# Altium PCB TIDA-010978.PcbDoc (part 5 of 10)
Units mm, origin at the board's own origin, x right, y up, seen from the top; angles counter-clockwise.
Board outline 243.95 x 94.85 mm, 4 copper layers (Top Layer, Mid Layer 1, Mid Layer 2, Bottom Layer), stack 1.623 mm thick; 865 components, 374 nets, 2308 pads, 2132 vias.
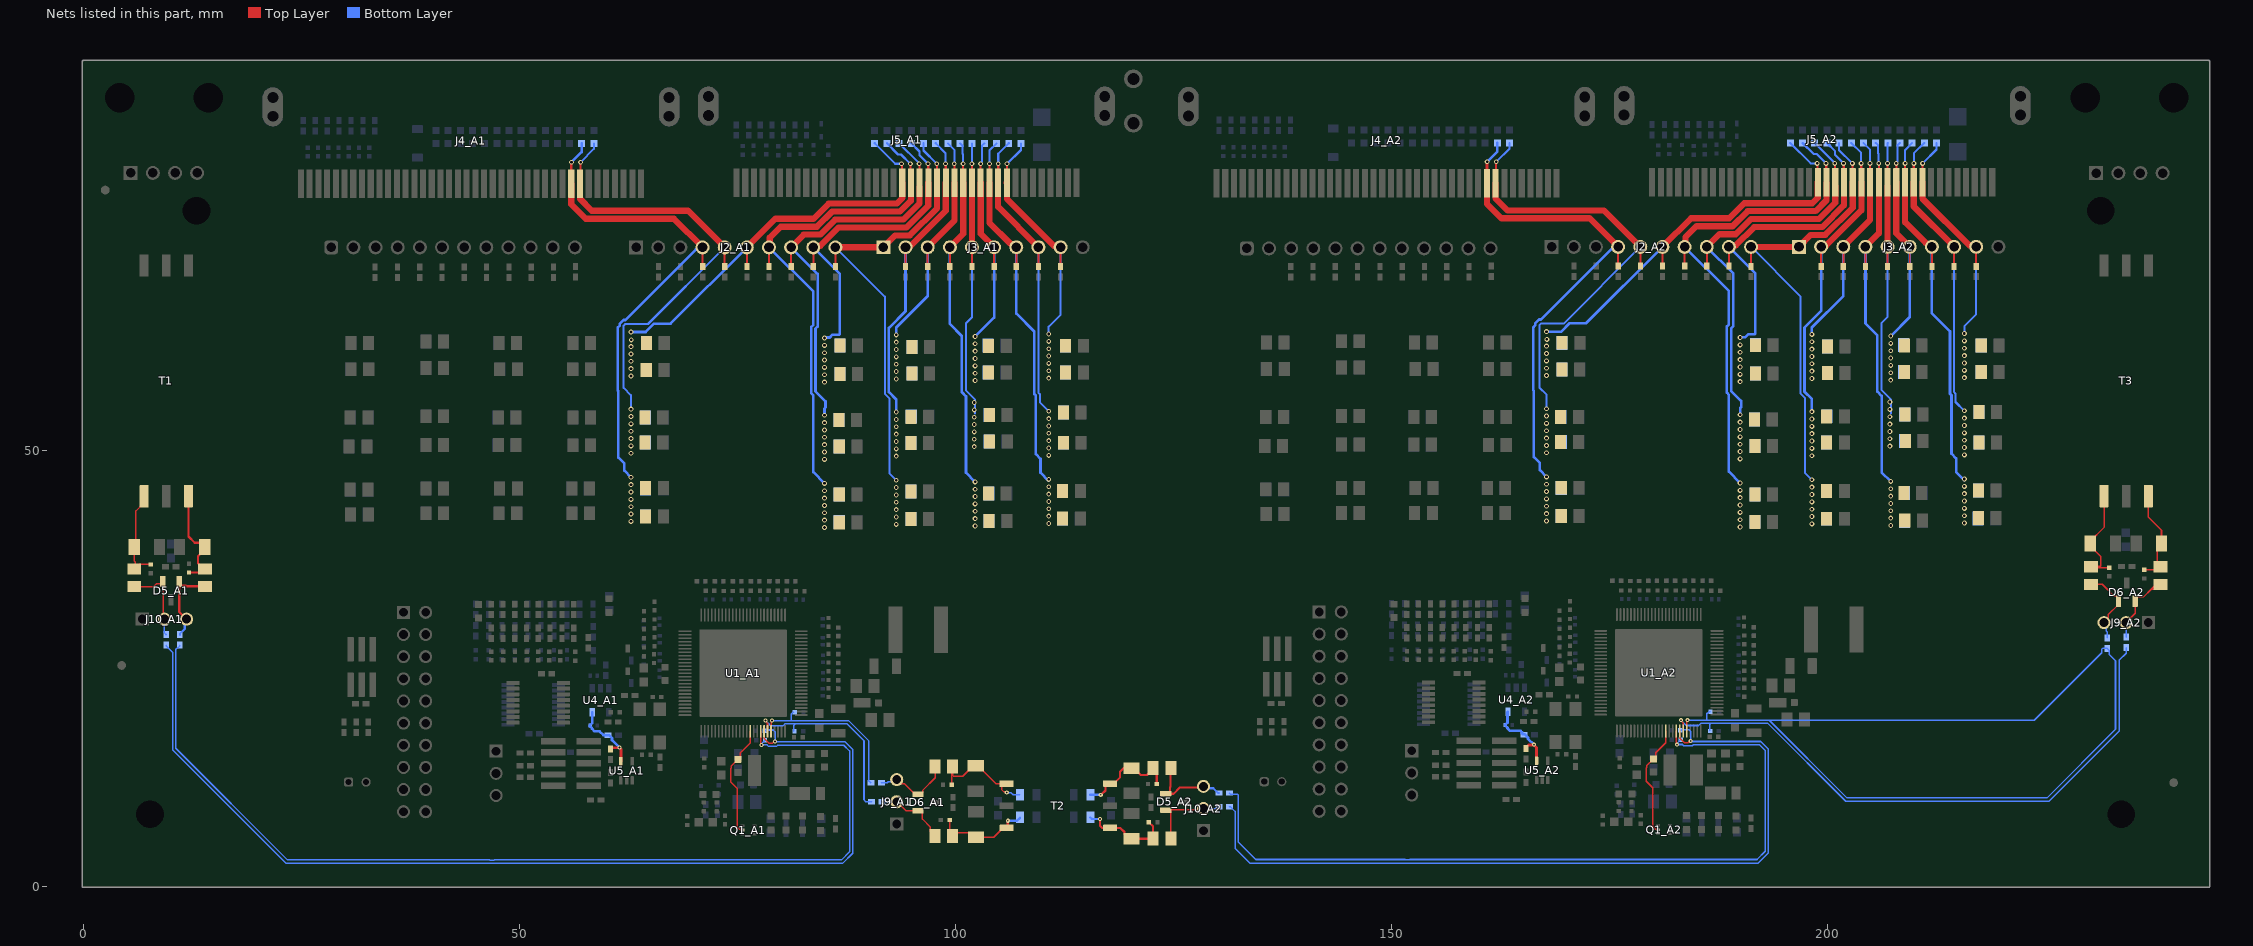
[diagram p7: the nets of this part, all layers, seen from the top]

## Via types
v1: diameter 0.559, hole 0.305, Top Layer to Bottom Layer, tented both sides, 1735 vias
v2: diameter 0.47, hole 0.2, Top Layer to Bottom Layer, tented both sides, 269 vias
v3: diameter 0.5, hole 0.2, Top Layer to Bottom Layer, tented both sides, 128 vias

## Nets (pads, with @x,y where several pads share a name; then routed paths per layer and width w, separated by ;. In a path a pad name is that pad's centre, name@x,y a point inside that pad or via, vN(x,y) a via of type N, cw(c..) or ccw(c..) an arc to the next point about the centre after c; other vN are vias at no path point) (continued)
CELL12_A1: C113_A1.2 J2_A1.4 J4_A1.16 R3_A1.1 R9_A1.1 R13_A1.1 R17_A1.1 R194_A1.1 | length 58.2
  Top Layer w0.229: J2_A1.4@70.993,73.282 71.002,73.273 71.002,71.076 R194_A1.1@71.011,71.067
  Top Layer w0.305: J4_A1.16@55.948,80.581 55.955,80.588 55.955,83.034 v1(55.967,83.046)
  Top Layer w0.711: J4_A1.16@55.948,80.581 55.948,78.226 57.612,76.562 67.714,76.562 J2_A1.4@70.993,73.282
  Bottom Layer w0.305: v1(55.967,83.046) 57.142,84.221 C113_A1.2@57.142,85.209 ; v1(62.782,46.911) 62.021,47.672 62.021,48.484 61.334,49.171 61.334,56.781 61.265,56.85 61.265,64.068 61.482,64.285 61.482,64.499 61.94,64.956 62.153,64.956 70.231,73.034 70.746,73.034 J2_A1.4@70.993,73.282
  other v1: 62.782,41.854 62.782,42.697 62.782,43.54 62.782,44.383 62.782,45.225 62.782,46.068
CELL12_A2: C113_A2.2 J2_A2.4 J4_A2.16 R3_A2.1 R9_A2.1 R13_A2.1 R17_A2.1 R194_A2.1 | length 58.2
  Top Layer w0.229: J2_A2.4@175.993,73.332 176.002,73.323 176.002,71.126 R194_A2.1@176.011,71.117
  Top Layer w0.305: J4_A2.16@160.948,80.631 160.955,80.638 160.955,83.084 v1(160.967,83.096)
  Top Layer w0.711: J4_A2.16@160.948,80.631 160.948,78.276 162.612,76.612 172.714,76.612 J2_A2.4@175.993,73.332
  Bottom Layer w0.305: v1(160.967,83.096) 162.142,84.271 C113_A2.2@162.142,85.259 ; v1(167.782,46.961) 167.021,47.722 167.021,48.534 166.334,49.221 166.334,56.831 166.265,56.9 166.265,64.118 166.482,64.335 166.482,64.549 166.94,65.006 167.153,65.006 175.231,73.084 175.746,73.084 J2_A2.4@175.993,73.332
  other v1: 167.782,41.904 167.782,42.747 167.782,43.59 167.782,44.433 167.782,45.275 167.782,46.118
CELL13_A1: C109_A1.2 J2_A1.5 J4_A1.37 R102_A1.1 R109_A1.1 R114_A1.1 R119_A1.1 R192_A1.1 | length 53.4
  Top Layer w0.229: J4_A1.37@56.942,80.587 56.979,80.624 56.979,83.01 v1(57.016,83.046) ; J2_A1.5@73.533,73.282 73.541,73.275 73.541,71.074 R192_A1.1@73.548,71.067
  Top Layer w0.711: J4_A1.37@56.942,80.587 56.942,78.83 58.299,77.473 69.342,77.473 J2_A1.5@73.533,73.282
  Bottom Layer w0.229: v1(57.016,83.046) 58.533,84.564 C109_A1.2@58.533,85.209 ; v1(62.782,54.727) 62.782,56.325 61.949,57.158 61.949,64.305 62.133,64.489 64.741,64.489 J2_A1.5@73.533,73.282
  other v1: 62.782,49.67 62.782,50.513 62.782,51.356 62.782,52.199 62.782,53.041 62.782,53.884
CELL13_A2: C109_A2.2 J2_A2.5 J4_A2.37 R102_A2.1 R109_A2.1 R114_A2.1 R119_A2.1 R192_A2.1 | length 53.4
  Top Layer w0.229: J4_A2.37@161.942,80.637 161.979,80.674 161.979,83.06 v1(162.016,83.096) ; J2_A2.5@178.533,73.332 178.541,73.325 178.541,71.124 R192_A2.1@178.548,71.117
  Top Layer w0.711: J4_A2.37@161.942,80.637 161.942,78.88 163.299,77.523 174.342,77.523 J2_A2.5@178.533,73.332
  Bottom Layer w0.229: v1(162.016,83.096) 163.533,84.614 C109_A2.2@163.533,85.259 ; v1(167.782,54.777) 167.782,56.375 166.949,57.208 166.949,64.355 167.133,64.539 169.741,64.539 J2_A2.5@178.533,73.332
  other v1: 167.782,49.72 167.782,50.563 167.782,51.406 167.782,52.249 167.782,53.091 167.782,53.934
CELL14_A1: C105_A1.2 J2_A1.6 J5_A1.10 R82_A1.1 R87_A1.1 R92_A1.1 R97_A1.1 R232_A1.1 | length 47.7
  Top Layer w0.229: J2_A1.6@76.073,73.282 76.079,73.276 76.079,71.073 R232_A1.1@76.085,71.067
  Top Layer w0.254: v1(93.817,82.862) 93.855,82.825 93.855,80.725 J5_A1.10@93.892,80.687
  Top Layer w0.711: J2_A1.6@76.073,73.282 79.353,76.562 83.73,76.562 85.464,78.296 93.258,78.296 93.887,78.924 93.887,80.681 J5_A1.10@93.892,80.687
  Bottom Layer w0.254: C105_A1.2@90.742,85.209 93.089,82.862 v1(93.817,82.862)
  Bottom Layer w0.305: v1(62.782,63.569) 64.48,63.569 65.439,64.527 67.319,64.527 J2_A1.6@76.073,73.282
  other v1: 62.782,58.528 62.782,59.371 62.782,60.214 62.782,61.057 62.782,61.9 62.826,62.674
CELL14_A2: C105_A2.2 J2_A2.6 J5_A2.10 R82_A2.1 R87_A2.1 R92_A2.1 R97_A2.1 R232_A2.1 | length 47.7
  Top Layer w0.229: J2_A2.6@181.073,73.332 181.079,73.326 181.079,71.123 R232_A2.1@181.085,71.117
  Top Layer w0.254: v1(198.817,82.912) 198.855,82.875 198.855,80.775 J5_A2.10@198.892,80.737
  Top Layer w0.711: J2_A2.6@181.073,73.332 184.353,76.612 188.73,76.612 190.464,78.346 198.258,78.346 198.887,78.974 198.887,80.731 J5_A2.10@198.892,80.737
  Bottom Layer w0.254: C105_A2.2@195.742,85.259 198.089,82.912 v1(198.817,82.912)
  Bottom Layer w0.305: v1(167.782,63.619) 169.48,63.619 170.439,64.577 172.319,64.577 J2_A2.6@181.073,73.332
  other v1: 167.782,58.578 167.782,59.421 167.782,60.264 167.782,61.107 167.782,61.95 167.826,62.724
CELL15_A1: C103_A1.2 J2_A1.7 J5_A1.31 R60_A1.1 R64_A1.1 R68_A1.1 R74_A1.1 R230_A1.1 | length 59.1
  Top Layer w0.229: J2_A1.7@78.613,73.282 78.618,73.278 78.618,71.071 R230_A1.1@78.622,71.067
  Top Layer w0.254: v1(94.826,82.862) 94.859,82.829 94.859,80.709 J5_A1.31@94.887,80.681
  Top Layer w0.711: J2_A1.7@78.613,73.282 78.713,73.381 78.713,74.4 79.963,75.651 84.108,75.651 85.842,77.385 93.636,77.385 94.887,78.636 J5_A1.31@94.887,80.681
  Bottom Layer w0.254: C103_A1.2@92.139,85.209 93.42,83.928 93.76,83.928 v1(94.826,82.862)
  Bottom Layer w0.305: J2_A1.7@78.613,73.282 83.696,68.199 83.696,64.404 83.451,64.159 83.451,56.562 83.696,56.317 83.696,47.5 v1(84.985,46.212)
  other v1: 84.985,41.154 84.985,41.997 84.985,42.84 84.985,43.683 84.985,44.526 84.985,45.369
CELL15_A2: C103_A2.2 J2_A2.7 J5_A2.31 R60_A2.1 R64_A2.1 R68_A2.1 R74_A2.1 R230_A2.1 | length 59.1
  Top Layer w0.229: J2_A2.7@183.613,73.332 183.618,73.328 183.618,71.121 R230_A2.1@183.622,71.117
  Top Layer w0.254: v1(199.826,82.912) 199.859,82.879 199.859,80.759 J5_A2.31@199.887,80.731
  Top Layer w0.711: J2_A2.7@183.613,73.332 183.713,73.431 183.713,74.45 184.963,75.701 189.108,75.701 190.842,77.435 198.636,77.435 199.887,78.686 J5_A2.31@199.887,80.731
  Bottom Layer w0.254: C103_A2.2@197.139,85.259 198.42,83.978 198.76,83.978 v1(199.826,82.912)
  Bottom Layer w0.305: J2_A2.7@183.613,73.332 188.696,68.249 188.696,64.454 188.451,64.209 188.451,56.612 188.696,56.367 188.696,47.55 v1(189.985,46.262)
  other v1: 189.985,41.204 189.985,42.047 189.985,42.89 189.985,43.733 189.985,44.576 189.985,45.419
CELL16_A1: C99_A1.2 J2_A1.8 J5_A1.11 R40_A1.1 R44_A1.1 R48_A1.1 R53_A1.1 R224_A1.1 | length 48
  Top Layer w0.229: J2_A1.8@81.153,73.282 81.156,73.279 81.156,71.07 R224_A1.1@81.159,71.067
  Top Layer w0.254: v1(95.834,82.862) 95.863,82.833 95.863,80.299 J5_A1.11@95.887,80.276
  Top Layer w0.711: J2_A1.8@81.153,73.282 82.611,74.74 84.485,74.74 86.219,76.473 94.013,76.473 95.887,78.347 J5_A1.11@95.887,80.276
  Bottom Layer w0.254: C99_A1.2@93.536,85.209 95.834,82.911 v1(95.834,82.862)
  Bottom Layer w0.305: J2_A1.8@81.153,73.282 84.201,70.234 84.201,64.195 83.956,63.95 83.956,56.771 85.1,55.627 85.1,54.919 84.985,54.804 v1(84.985,54.028)
  other v1: 84.985,48.97 84.985,49.813 84.985,50.656 84.985,51.499 84.985,52.342 84.985,53.185
CELL16_A2: C99_A2.2 J2_A2.8 J5_A2.11 R40_A2.1 R44_A2.1 R48_A2.1 R53_A2.1 R224_A2.1 | length 48
  Top Layer w0.229: J2_A2.8@186.153,73.332 186.156,73.329 186.156,71.12 R224_A2.1@186.159,71.117
  Top Layer w0.254: v1(200.834,82.912) 200.863,82.883 200.863,80.349 J5_A2.11@200.887,80.326
  Top Layer w0.711: J2_A2.8@186.153,73.332 187.611,74.79 189.485,74.79 191.219,76.523 199.013,76.523 200.887,78.397 J5_A2.11@200.887,80.326
  Bottom Layer w0.254: C99_A2.2@198.536,85.259 200.834,82.961 v1(200.834,82.912)
  Bottom Layer w0.305: J2_A2.8@186.153,73.332 189.201,70.284 189.201,64.245 188.956,64 188.956,56.821 190.1,55.677 190.1,54.969 189.985,54.854 v1(189.985,54.078)
  other v1: 189.985,49.02 189.985,49.863 189.985,50.706 189.985,51.549 189.985,52.392 189.985,53.235
CELL17_A1: C96_A1.2 J2_A1.9 J5_A1.32 R23_A1.1 R27_A1.1 R31_A1.1 R35_A1.1 R220_A1.1 | length 38.5
  Top Layer w0.229: J2_A1.9@83.693,73.282 83.695,73.281 83.695,71.068 R220_A1.1@83.696,71.067
  Top Layer w0.254: v1(96.842,82.862) 96.867,82.837 96.867,80.701 J5_A1.32@96.887,80.681
  Top Layer w0.711: J2_A1.9@83.693,73.282 83.863,73.452 84.486,73.452 86.596,75.562 94.39,75.562 96.887,78.059 J5_A1.32@96.887,80.681
  Bottom Layer w0.254: C96_A1.2@94.934,85.209 95.877,84.265 95.877,83.828 v1(96.842,82.862)
  Bottom Layer w0.305: J2_A1.9@83.693,73.282 86.735,70.241 86.735,63.347 86.658,63.27 85.917,63.27 85.582,62.935 85.033,62.935 v1(84.985,62.886)
  other v1: 84.985,57.829 84.985,58.671 84.985,59.514 84.985,60.357 84.985,61.2 84.985,62.043
CELL17_A2: C96_A2.2 J2_A2.9 J5_A2.32 R23_A2.1 R27_A2.1 R31_A2.1 R35_A2.1 R220_A2.1 | length 38.5
  Top Layer w0.229: J2_A2.9@188.693,73.332 188.695,73.331 188.695,71.118 R220_A2.1@188.696,71.117
  Top Layer w0.254: v1(201.842,82.912) 201.867,82.887 201.867,80.751 J5_A2.32@201.887,80.731
  Top Layer w0.711: J2_A2.9@188.693,73.332 188.863,73.502 189.486,73.502 191.596,75.612 199.39,75.612 201.887,78.109 J5_A2.32@201.887,80.731
  Bottom Layer w0.254: C96_A2.2@199.934,85.259 200.877,84.315 200.877,83.878 v1(201.842,82.912)
  Bottom Layer w0.305: J2_A2.9@188.693,73.332 191.735,70.291 191.735,63.397 191.658,63.32 190.917,63.32 190.582,62.985 190.033,62.985 v1(189.985,62.936)
  other v1: 189.985,57.879 189.985,58.721 189.985,59.564 189.985,60.407 189.985,61.25 189.985,62.093
CELL18_A1: C93_A1.2 J2_A1.10 J3_A1.1 J5_A1.12 R4_A1.1 R10_A1.1 R14_A1.1 R18_A1.1 R217_A1.1 | length 53.4
  Top Layer w0.229: R217_A1.1@86.233,71.067 J2_A1.10@86.233,73.282
  Top Layer w0.254: v1(97.851,82.862) 97.871,82.841 97.871,80.708 J5_A1.12@97.892,80.687
  Top Layer w0.711: J2_A1.10@86.233,73.282 86.24,73.289 91.728,73.289 J3_A1.1@91.735,73.295 93.09,74.651 94.768,74.651 97.892,77.775 J5_A1.12@97.892,80.687
  Bottom Layer w0.229: J2_A1.10@86.233,73.282 91.896,67.62 91.896,56.48 92.446,55.93 92.446,47.34 v1(93.21,46.576)
  Bottom Layer w0.254: C93_A1.2@96.331,85.209 96.331,84.382 v1(97.851,82.862)
  other v1: 93.21,41.519 93.21,42.362 93.21,43.204 93.21,44.047 93.21,44.89 93.21,45.733
CELL18_A2: C93_A2.2 J2_A2.10 J3_A2.1 J5_A2.12 R4_A2.1 R10_A2.1 R14_A2.1 R18_A2.1 R217_A2.1 | length 53.4
  Top Layer w0.229: R217_A2.1@191.233,71.117 J2_A2.10@191.233,73.332
  Top Layer w0.254: v1(202.851,82.912) 202.871,82.891 202.871,80.758 J5_A2.12@202.892,80.737
  Top Layer w0.711: J2_A2.10@191.233,73.332 191.24,73.339 196.728,73.339 J3_A2.1@196.735,73.345 198.09,74.701 199.768,74.701 202.892,77.825 J5_A2.12@202.892,80.737
  Bottom Layer w0.229: J2_A2.10@191.233,73.332 196.896,67.67 196.896,56.53 197.446,55.98 197.446,47.39 v1(198.21,46.626)
  Bottom Layer w0.254: C93_A2.2@201.331,85.259 201.331,84.432 v1(202.851,82.912)
  other v1: 198.21,41.569 198.21,42.412 198.21,43.254 198.21,44.097 198.21,44.94 198.21,45.783
CELL19_A1: C90_A1.2 J3_A1.2 J5_A1.33 R103_A1.1 R110_A1.1 R115_A1.1 R120_A1.1 R214_A1.1 | length 36.8
  Top Layer w0.229: R214_A1.1@94.275,71.062 J3_A1.2@94.275,73.295
  Top Layer w0.254: v1(98.859,82.862) 98.876,82.845 98.876,80.704 J5_A1.33@98.892,80.687
  Top Layer w0.711: J3_A1.2@94.275,73.295 94.445,73.465 94.871,73.465 98.892,77.487 J5_A1.33@98.892,80.687
  Bottom Layer w0.254: C90_A1.2@97.728,85.209 98.859,84.077 v1(98.859,82.862)
  Bottom Layer w0.305: v1(93.21,54.392) 93.21,55.825 92.362,56.673 92.362,64.041 94.275,65.953 J3_A1.2@94.275,73.295
  other v1: 93.21,49.335 93.21,50.178 93.21,51.02 93.21,51.863 93.21,52.706 93.21,53.549
CELL19_A2: C90_A2.2 J3_A2.2 J5_A2.33 R103_A2.1 R110_A2.1 R115_A2.1 R120_A2.1 R214_A2.1 | length 36.8
  Top Layer w0.229: R214_A2.1@199.275,71.112 J3_A2.2@199.275,73.345
  Top Layer w0.254: v1(203.859,82.912) 203.876,82.895 203.876,80.754 J5_A2.33@203.892,80.737
  Top Layer w0.711: J3_A2.2@199.275,73.345 199.445,73.515 199.871,73.515 203.892,77.537 J5_A2.33@203.892,80.737
  Bottom Layer w0.254: C90_A2.2@202.728,85.259 203.859,84.127 v1(203.859,82.912)
  Bottom Layer w0.305: v1(198.21,54.442) 198.21,55.875 197.362,56.723 197.362,64.091 199.275,66.003 J3_A2.2@199.275,73.345
  other v1: 198.21,49.385 198.21,50.228 198.21,51.07 198.21,51.913 198.21,52.756 198.21,53.599
CELL20_A1: C87_A1.2 J3_A1.3 J5_A1.13 R83_A1.1 R88_A1.1 R93_A1.1 R98_A1.1 R208_A1.1 | length 27.3
  Top Layer w0.229: R208_A1.1@96.815,71.062 J3_A1.3@96.815,73.295 ; v1(99.867,82.862) 99.88,82.85 99.88,80.7 J5_A1.13@99.892,80.687
  Top Layer w0.711: J3_A1.3@96.815,73.295 99.892,76.373 J5_A1.13@99.892,80.687
  Bottom Layer w0.229: C87_A1.2@99.125,85.209 99.867,84.466 v1(99.867,82.862)
  Bottom Layer w0.305: v1(93.21,63.25) 93.21,64.069 96.815,67.673 J3_A1.3@96.815,73.295
  other v1: 93.21,58.193 93.21,59.036 93.21,59.879 93.21,60.722 93.21,61.565 93.21,62.407
CELL20_A2: C87_A2.2 J3_A2.3 J5_A2.13 R83_A2.1 R88_A2.1 R93_A2.1 R98_A2.1 R208_A2.1 | length 27.3
  Top Layer w0.229: R208_A2.1@201.815,71.112 J3_A2.3@201.815,73.345 ; v1(204.867,82.912) 204.88,82.9 204.88,80.75 J5_A2.13@204.892,80.737
  Top Layer w0.711: J3_A2.3@201.815,73.345 204.892,76.423 J5_A2.13@204.892,80.737
  Bottom Layer w0.229: C87_A2.2@204.125,85.259 204.867,84.516 v1(204.867,82.912)
  Bottom Layer w0.305: v1(198.21,63.3) 198.21,64.119 201.815,67.723 J3_A2.3@201.815,73.345
  other v1: 198.21,58.243 198.21,59.086 198.21,59.929 198.21,60.772 198.21,61.615 198.21,62.457
CELL21_A1: C85_A1.2 J3_A1.4 J5_A1.34 R61_A1.1 R65_A1.1 R69_A1.1 R75_A1.1 R206_A1.1 | length 43
  Top Layer w0.229: R206_A1.1@99.355,71.062 J3_A1.4@99.355,73.295 ; v1(100.876,82.862) 100.884,82.854 100.884,80.695 J5_A1.34@100.892,80.687
  Top Layer w0.711: J3_A1.4@99.355,73.295 100.892,74.833 J5_A1.34@100.892,80.687
  Bottom Layer w0.229: C85_A1.2@100.522,85.209 100.808,84.923 100.808,84.003 100.876,83.935 v1(100.876,82.862)
  Bottom Layer w0.305: J3_A1.4@99.355,73.295 99.355,64.502 100.721,63.136 100.721,56.684 101.212,56.193 101.212,47.435 v1(102.257,46.39)
  other v1: 102.257,41.333 102.257,42.176 102.257,43.019 102.257,43.861 102.257,44.704 102.257,45.547
CELL21_A2: C85_A2.2 J3_A2.4 J5_A2.34 R61_A2.1 R65_A2.1 R69_A2.1 R75_A2.1 R206_A2.1 | length 43
  Top Layer w0.229: R206_A2.1@204.355,71.112 J3_A2.4@204.355,73.345 ; v1(205.876,82.912) 205.884,82.904 205.884,80.745 J5_A2.34@205.892,80.737
  Top Layer w0.711: J3_A2.4@204.355,73.345 205.892,74.883 J5_A2.34@205.892,80.737
  Bottom Layer w0.229: C85_A2.2@205.522,85.259 205.808,84.973 205.808,84.053 205.876,83.985 v1(205.876,82.912)
  Bottom Layer w0.305: J3_A2.4@204.355,73.345 204.355,64.552 205.721,63.186 205.721,56.734 206.212,56.243 206.212,47.485 v1(207.257,46.44)
  other v1: 207.257,41.383 207.257,42.226 207.257,43.069 207.257,43.911 207.257,44.754 207.257,45.597
CELL22_A1: C83_A1.2 J3_A1.5 J5_A1.14 R41_A1.1 R45_A1.1 R49_A1.1 R54_A1.1 R204_A1.1 | length 34
  Top Layer w0.229: v1(101.884,82.862) 101.888,82.858 101.888,80.281 J5_A1.14@101.894,80.276 ; R204_A1.1@101.895,71.062 J3_A1.5@101.895,73.295
  Top Layer w0.711: J5_A1.14@101.894,80.276 J3_A1.5@101.895,73.295 J3_A1.5@101.895,73.295
  Bottom Layer w0.229: v1(101.884,82.862) 101.884,85.173 C83_A1.2@101.919,85.209 ; J3_A1.5@101.895,73.295 101.895,65.254 101.188,64.548 101.188,56.878 102.257,55.808 102.257,54.206
  other v1: 102.153,50.433 102.153,51.276 102.153,52.119 102.153,52.962 102.153,53.805 102.153,54.648 102.153,55.491
CELL22_A2: C83_A2.2 J3_A2.5 J5_A2.14 R41_A2.1 R45_A2.1 R49_A2.1 R54_A2.1 R204_A2.1 | length 34
  Top Layer w0.229: v1(206.884,82.912) 206.888,82.908 206.888,80.331 J5_A2.14@206.894,80.326 ; R204_A2.1@206.895,71.112 J3_A2.5@206.895,73.345
  Top Layer w0.711: J5_A2.14@206.894,80.326 206.894,73.347 J3_A2.5@206.895,73.345
  Bottom Layer w0.229: v1(206.884,82.912) 206.884,85.223 C83_A2.2@206.919,85.259 ; J3_A2.5@206.895,73.345 206.895,65.304 206.188,64.598 206.188,56.928 207.257,55.858 207.257,54.256
  other v1: 207.153,50.483 207.153,51.326 207.153,52.169 207.153,53.012 207.153,53.855 207.153,54.698 207.153,55.541
CELL23_A1: C79_A1.2 J3_A1.6 J5_A1.35 R24_A1.1 R28_A1.1 R32_A1.1 R36_A1.1 R202_A1.1 | length 26.1
  Top Layer w0.229: J5_A1.35@102.892,80.687 v1(102.892,82.862) ; R202_A1.1@104.435,71.062 J3_A1.6@104.435,73.295
  Top Layer w0.711: J5_A1.35@102.892,80.687 102.892,74.838 J3_A1.6@104.435,73.295
  Bottom Layer w0.229: v1(102.892,82.862) 102.892,82.951 103.03,83.09 103.03,84.923 C79_A1.2@103.316,85.209
  Bottom Layer w0.305: v1(102.257,63.065) 104.435,65.242 J3_A1.6@104.435,73.295
  other v1: 102.257,58.007 102.257,58.85 102.257,59.693 102.257,60.536 102.257,61.379 102.257,62.222
CELL23_A2: C79_A2.2 J3_A2.6 J5_A2.35 R24_A2.1 R28_A2.1 R32_A2.1 R36_A2.1 R202_A2.1 | length 26.1
  Top Layer w0.229: J5_A2.35@207.892,80.737 v1(207.892,82.912) ; R202_A2.1@209.435,71.112 J3_A2.6@209.435,73.345
  Top Layer w0.711: J5_A2.35@207.892,80.737 207.892,74.888 J3_A2.6@209.435,73.345
  Bottom Layer w0.229: v1(207.892,82.912) 207.892,83.001 208.03,83.14 208.03,84.973 C79_A2.2@208.316,85.259
  Bottom Layer w0.305: v1(207.257,63.115) 209.435,65.292 J3_A2.6@209.435,73.345
  other v1: 207.257,58.057 207.257,58.9 207.257,59.743 207.257,60.586 207.257,61.429 207.257,62.272
CELL24_A1: C75_A1.2 J3_A1.7 J5_A1.15 R5_A1.1 R11_A1.1 R15_A1.1 R19_A1.1 R200_A1.1 | length 44.4
  Top Layer w0.229: J5_A1.15@103.892,80.687 103.896,80.691 103.896,82.858 v1(103.901,82.862) ; R200_A1.1@106.975,71.062 J3_A1.7@106.975,73.295
  Top Layer w0.711: J5_A1.15@103.892,80.687 103.892,76.1 106.252,73.74 106.29,73.74 106.734,73.295 J3_A1.7@106.975,73.295
  Bottom Layer w0.229: v1(103.901,82.862) 103.901,84.396 C75_A1.2@104.713,85.209
  Bottom Layer w0.305: J3_A1.7@106.975,73.295 106.975,65.67 109.043,63.602 109.043,56.444 109.217,56.27 109.217,49.569 109.756,49.029 109.756,47.447 110.693,46.51 v1(110.693,46.671)
  other v1: 110.693,41.613 110.693,42.456 110.693,43.299 110.693,44.142 110.693,44.985 110.693,45.828
CELL24_A2: C75_A2.2 J3_A2.7 J5_A2.15 R5_A2.1 R11_A2.1 R15_A2.1 R19_A2.1 R200_A2.1 | length 44.4
  Top Layer w0.229: J5_A2.15@208.892,80.737 208.896,80.741 208.896,82.908 v1(208.901,82.912) ; R200_A2.1@211.975,71.112 J3_A2.7@211.975,73.345
  Top Layer w0.711: J5_A2.15@208.892,80.737 208.892,76.15 211.252,73.79 211.29,73.79 211.734,73.345 J3_A2.7@211.975,73.345
  Bottom Layer w0.229: v1(208.901,82.912) 208.901,84.446 C75_A2.2@209.713,85.259
  Bottom Layer w0.305: J3_A2.7@211.975,73.345 211.975,65.72 214.043,63.652 214.043,56.494 214.217,56.32 214.217,49.619 214.756,49.079 214.756,47.497 215.693,46.56 v1(215.693,46.721)
  other v1: 215.693,41.663 215.693,42.506 215.693,43.349 215.693,44.192 215.693,45.035 215.693,45.878
CELL25_A1: C71_A1.2 J3_A1.8 J5_A1.36 R104_A1.1 R111_A1.1 R116_A1.1 R121_A1.1 R198_A1.1 | length 35.9
  Top Layer w0.229: R198_A1.1@109.515,71.062 J3_A1.8@109.515,73.295
  Top Layer w0.254: J5_A1.36@104.892,80.687 104.901,80.695 104.901,82.854 v1(104.909,82.862)
  Top Layer w0.711: J5_A1.36@104.892,80.687 104.892,77.918 J3_A1.8@109.515,73.295
  Bottom Layer w0.229: J3_A1.8@109.515,73.295 109.515,56.632 109.683,56.463 109.683,55.496 v1(110.693,54.487)
  Bottom Layer w0.254: v1(104.909,82.862) 104.909,84.007 C71_A1.2@106.11,85.209
  other v1: 110.693,49.429 110.693,50.272 110.693,51.115 110.693,51.958 110.693,52.801 110.693,53.644
CELL25_A2: C71_A2.2 J3_A2.8 J5_A2.36 R104_A2.1 R111_A2.1 R116_A2.1 R121_A2.1 R198_A2.1 | length 35.9
  Top Layer w0.229: R198_A2.1@214.515,71.112 J3_A2.8@214.515,73.345
  Top Layer w0.254: J5_A2.36@209.892,80.737 209.901,80.745 209.901,82.904 v1(209.909,82.912)
  Top Layer w0.711: J5_A2.36@209.892,80.737 209.892,77.968 J3_A2.8@214.515,73.345
  Bottom Layer w0.229: J3_A2.8@214.515,73.345 214.515,56.682 214.683,56.513 214.683,55.546 v1(215.693,54.537)
  Bottom Layer w0.254: v1(209.909,82.912) 209.909,84.057 C71_A2.2@211.11,85.259
  other v1: 215.693,49.479 215.693,50.322 215.693,51.165 215.693,52.008 215.693,52.851 215.693,53.694
CELL26_A1: C70_A1.2 J3_A1.9 J5_A1.16 R84_A1.1 R89_A1.1 R94_A1.1 R99_A1.1 R195_A1.1 | length 28.2
  Top Layer w0.229: R195_A1.1@112.055,71.062 J3_A1.9@112.055,73.295
  Top Layer w0.254: J5_A1.16@105.892,80.687 105.905,80.7 105.905,82.85 v1(105.917,82.862)
  Top Layer w0.711: J5_A1.16@105.892,80.687 105.898,80.681 105.898,78.829 111.262,73.465 111.885,73.465 J3_A1.9@112.055,73.295
  Bottom Layer w0.229: v1(110.693,63.345) 110.693,64.18 112.055,65.542 J3_A1.9@112.055,73.295
  Bottom Layer w0.254: v1(105.917,82.862) 107.507,84.452 C70_A1.2@107.507,85.197
  other v1: 110.693,58.288 110.693,59.131 110.693,59.973 110.693,60.816 110.693,61.659 110.693,62.502
CELL26_A2: C70_A2.2 J3_A2.9 J5_A2.16 R84_A2.1 R89_A2.1 R94_A2.1 R99_A2.1 R195_A2.1 | length 28.2
  Top Layer w0.229: R195_A2.1@217.055,71.112 J3_A2.9@217.055,73.345
  Top Layer w0.254: J5_A2.16@210.892,80.737 210.905,80.75 210.905,82.9 v1(210.917,82.912)
  Top Layer w0.711: J5_A2.16@210.892,80.737 210.898,80.731 210.898,78.879 216.262,73.515 216.885,73.515 J3_A2.9@217.055,73.345
  Bottom Layer w0.229: v1(215.693,63.395) 215.693,64.23 217.055,65.592 J3_A2.9@217.055,73.345
  Bottom Layer w0.254: v1(210.917,82.912) 212.507,84.502 C70_A2.2@212.507,85.247
  other v1: 215.693,58.338 215.693,59.181 215.693,60.023 215.693,60.866 215.693,61.709 215.693,62.552
COMH_A1_N: C151_A1.2 R227_A1.1 U1_A1.95 | length 22.4
  Top Layer w0.178: v2(78.214,19.014) 78.214,18.935 78.446,18.702 78.446,17.785 U1_A1.95@78.457,17.774
  Bottom Layer w0.178: v2(78.214,19.014) 78.7,18.528 78.7,18.503 78.804,18.399 80.22,18.399 80.457,18.636 81.624,18.636 ; C151_A1.2@81.478,17.806 81.478,18.49 81.624,18.636 ; R227_A1.1@90.391,9.702 89.724,9.702 89.509,9.917 89.509,16.701 87.574,18.636 81.624,18.636
COMH_A1_P: C139_A1.1 R211_A1.1 U1_A1.96 | length 19.4
  Top Layer w0.178: U1_A1.96@78.857,17.774 78.868,17.785 78.868,18.848 78.955,18.935 v2(78.955,19.014)
  Bottom Layer w0.178: v2(78.955,19.014) 80.327,19.014 81.161,19.014 ; C139_A1.1@81.479,19.959 81.379,19.959 81.168,19.748 81.168,19.648 81.161,19.641 81.161,19.014 ; R211_A1.1@90.306,11.874 90.285,11.874 90.074,12.085 90.074,16.67 87.731,19.014 81.161,19.014
COMH_A2_N: C151_A2.2 R227_A2.1 U1_A2.95 | length 69.8
  Top Layer w0.178: v2(183.214,19.064) 183.214,18.985 183.446,18.752 183.446,17.835 U1_A2.95@183.457,17.824
  Bottom Layer w0.178: v2(183.214,19.064) 183.7,18.578 183.7,18.553 183.804,18.449 185.22,18.449 185.457,18.686 186.624,18.686 ; C151_A2.2@186.478,17.856 186.478,18.54 186.624,18.686 ; R227_A2.1@234.25,27.375 234.25,26.725 233.471,25.946 233.471,17.824 225.41,9.762 202.089,9.762 193.165,18.686 186.624,18.686
COMH_A2_P: C139_A2.1 R211_A2.1 U1_A2.96 | length 110.6
  Top Layer w0.178: U1_A2.96@183.857,17.824 183.868,17.835 183.868,18.898 183.955,18.985 v2(183.955,19.064)
  Bottom Layer w0.178: v2(183.955,19.064) 185.327,19.064 186.161,19.064 ; C139_A2.1@186.579,20.009 186.479,20.009 186.379,20.009 186.168,19.798 186.168,19.698 186.161,19.691 186.161,19.064 ; 193.322,19.064 202.246,10.14 225.165,10.14 233.031,18.006 233.031,25.875 232.29,26.616 232.29,27.079 R211_A2.1@232.079,27.29 231.547,27.29 231.443,27.186 231.443,26.783 223.724,19.064 186.161,19.064
COML_A1_N: C150_A1.2 R226_A1.2 U1_A1.94 | length 122
  Top Layer w0.178: U1_A1.94@78.057,17.774 78.068,17.762 78.068,16.958 78.606,16.421 78.984,16.421 79.121,16.558 79.252,16.558 v2(79.308,16.614)
  Bottom Layer w0.178: R226_A1.2@9.494,27.658 9.494,27.558 10.217,26.835 10.217,15.674 23.263,2.627 87.051,2.627 88.232,3.808 88.232,4.741 88.232,6.25 88.232,15.684 87.354,16.562 79.439,16.562 v2@79.373,16.628 ; C150_A1.2@78.231,17.85 78.316,17.934 79.086,17.934 79.308,17.712 79.308,16.744 79.373,16.679 v2(79.308,16.614)
COML_A1_P: C138_A1.1 R209_A1.2 U1_A1.93 | length 119.4
  Top Layer w0.178: U1_A1.93@77.657,17.774 77.657,16.371 77.754,16.274 v2(77.754,16.201)
  Bottom Layer w0.178: R209_A1.2@11.056,27.659 11.056,27.559 10.845,27.348 10.745,27.348 10.595,27.197 10.595,15.83 23.391,3.034 46.59,3.034 46.614,3.01 47.085,3.01 47.109,3.034 86.923,3.034 87.854,3.965 87.854,15.528 87.198,16.184 79.619,16.184 79.525,16.09 78.518,16.09 78.389,16.219 v2@77.772,16.219 ; v2(77.754,16.201) 77.786,16.233 77.786,16.389 C138_A1.1@78.157,16.76
COML_A2_N: C150_A2.2 R226_A2.2 U1_A2.94 | length 93.3
  Top Layer w0.178: U1_A2.94@183.057,17.824 183.068,17.812 183.068,17.008 183.606,16.471 183.984,16.471 184.121,16.608 184.252,16.608 v2(184.308,16.664)
  Bottom Layer w0.178: R226_A2.2@131.426,9.132 131.526,9.132 132.062,8.597 132.062,4.361 133.746,2.677 192.051,2.677 193.232,3.858 193.232,15.734 192.354,16.612 184.439,16.612 v2@184.373,16.678 ; C150_A2.2@183.231,17.9 183.316,17.984 184.086,17.984 184.308,17.762 184.308,16.794 184.373,16.729 v2(184.308,16.664)
COML_A2_P: C138_A2.1 R209_A2.2 U1_A2.93 | length 92.5
  Top Layer w0.178: U1_A2.93@182.657,17.824 182.657,16.421 182.754,16.324 v2(182.754,16.251)
  Bottom Layer w0.178: R209_A2.2@131.425,10.694 131.53,10.59 132.336,10.59 132.44,10.486 132.44,5.087 134.443,3.084 151.59,3.084 151.614,3.06 152.085,3.06 152.109,3.084 191.923,3.084 192.854,4.015 192.854,15.578 192.198,16.234 184.619,16.234 184.525,16.14 183.518,16.14 183.389,16.269 v2@182.772,16.269 ; v2(182.754,16.251) v2@182.772,16.269 ; C138_A2.1@183.157,16.81 182.786,16.439 182.786,16.283 v2@182.772,16.269
COMMH_A1_N: D6_A1.2 J9_A1.2 R227_A1.2 R228_A1.1 | length 8.4
  Top Layer w0.178: J9_A1.2@93.264,9.702 93.296,9.702 94.327,8.671 96.003,8.671 96.214,8.46 96.214,7.715 97.091,6.837 97.091,6.312 R228_A1.1@97.638,5.766
  Bottom Layer w0.178: R227_A1.2@91.591,9.702 J9_A1.2@93.264,9.702
COMMH_A1_P: D6_A1.1 J9_A1.3 R211_A1.2 R212_A1.1 | length 8.9
  Top Layer w0.178: J9_A1.3@93.264,12.242 93.296,12.242 93.77,11.769 94.156,11.769 95.354,10.571 D6_A1.1@95.704,10.571 ; D6_A1.1@96.03,10.548 96.265,10.783 96.265,11.045 97.676,12.456 97.676,13.688 R212_A1.1@97.638,13.727
  Bottom Layer w0.178: R211_A1.2@91.506,11.874 92.177,11.874 92.293,11.989 93.011,11.989 J9_A1.3@93.264,12.242
COMMH_A2_N: D6_A2.2 J9_A2.2 R227_A2.2 R228_A2.1 | length 16.5
  Top Layer w0.178: R228_A2.1@237.806,34.601 237.641,34.601 236.237,33.198 ; R228_A2.1@238.186,34.622 237.64,34.076 237.115,34.076 236.237,33.198 ; J9_A2.2@234.25,30.281 J9_A2.2@234.25,30.248 J9_A2.2@234.25,30.281 ; J9_A2.2@234.25,30.281 235.281,31.312 ; J9_A2.2@234.25,30.281 235.281,31.312 ; 235.281,31.312 D6_A2.2@235.281,32.987 ; 235.281,31.312 D6_A2.2@235.281,32.987 ; D6_A2.2@235.281,32.987 D6_A2.2@235.492,33.198 ; D6_A2.2@235.281,32.987 D6_A2.2@235.492,33.198 ; D6_A2.2@235.492,33.198 236.237,33.198 ; D6_A2.2@235.492,33.198 236.237,33.198
  Bottom Layer w0.178: R227_A2.2@234.25,28.575 J9_A2.2@234.25,30.248 R227_A2.2@234.25,28.575
COMMH_A2_P: D6_A2.1 J9_A2.3 R211_A2.2 R212_A2.1 | length 16.7
  Top Layer w0.178: R212_A2.1@230.226,34.622 230.264,34.66 231.496,34.66 ; 231.331,34.66 231.496,34.66 ; 231.496,34.66 232.908,33.249 ; 231.496,34.66 232.908,33.249 ; J9_A2.3@231.71,30.281 J9_A2.3@231.71,30.248 J9_A2.3@231.71,30.281 ; J9_A2.3@231.71,30.281 J9_A2.3@232.183,30.754 ; J9_A2.3@231.71,30.281 J9_A2.3@232.183,30.754 ; J9_A2.3@232.183,30.754 232.183,31.14 ; J9_A2.3@232.183,30.754 232.183,31.14 ; 232.183,31.14 D6_A2.1@233.381,32.338 ; 232.183,31.14 D6_A2.1@233.381,32.338 ; 232.908,33.249 D6_A2.1@233.17,33.249 ; 232.908,33.249 D6_A2.1@233.17,33.249 ; D6_A2.1@233.17,33.249 233.404,33.015 D6_A2.1@233.17,33.249 ; D6_A2.1@233.381,32.338 D6_A2.1@233.381,32.688 D6_A2.1@233.381,32.338
  Bottom Layer w0.178: 231.963,29.277 J9_A2.3@231.963,29.995 ; 231.963,29.277 232.079,29.161 ; 231.963,29.277 J9_A2.3@231.963,29.995 ; 231.963,29.277 232.079,29.161 ; J9_A2.3@231.963,29.995 J9_A2.3@231.71,30.248 J9_A2.3@231.963,29.995 ; 232.079,29.161 R211_A2.2@232.079,28.49 232.079,29.161
COMMH_N_OPT_A1: C6.1 C154_A1.2 R222_A1.1 R228_A1.2 T2.3 | length 11.5
  Top Layer w0.178: C154_A1.2@99.325,7.612 99.325,6.11 R228_A1.2@99.67,5.766 100.05,6.146 101.834,6.146 R222_A1.1@102.335,5.646 104.394,5.646 105.593,6.845 T2.3@106.006,6.845
  Top Layer w0.254: T2.3@106.006,6.845 v2(106.006,7.525)
  Bottom Layer w0.254: v2(106.006,7.525) 107.068,7.525 107.391,7.848 C6.1@107.391,7.915
COMMH_N_OPT_A2: C154_A2.2 R222_A2.1 R228_A2.2 T3.6 | length 11.5
  Top Layer w0.178: C154_A2.2@236.341,36.309 237.842,36.309 R228_A2.2@238.186,36.654 R228_A2.2@237.806,37.034 ; T3.6@236.796,44.75 236.796,42.357 238.307,40.847 238.307,40.494 R222_A2.1@238.307,39.319 237.806,38.818 R228_A2.2@237.806,37.034 ; R228_A2.2@237.806,36.633 R228_A2.2@237.806,37.034
COMMH_P_OPT_A1: C1.1 C147_A1.1 R212_A1.2 R218_A1.2 T2.1 | length 13.4
  Top Layer w0.178: C147_A1.1@99.575,11.636 99.575,13.632 R212_A1.2@99.67,13.727 99.708,13.688 99.708,12.726 99.812,12.621 100.844,12.621 R218_A1.2@102.044,13.821 ; R218_A1.2@102.319,13.821 102.594,13.821 104.634,11.782 T2.1@105.329,11.782 ; T2.1@105.863,11.782 T2.1@105.329,11.782 ; v2(105.881,10.776) 105.825,10.831 105.556,10.831 105.329,11.059 T2.1@105.329,11.782
  Bottom Layer w0.178: v2(105.881,10.776) 105.908,10.749 106.382,10.749 106.634,10.497 C1.1@107.391,10.497
COMMH_P_OPT_A2: C147_A2.1 R212_A2.2 R218_A2.2 T3.4 | length 15
  Top Layer w0.178: R218_A2.2@230.131,39.303 230.131,39.578 231.716,41.164 T3.4@231.716,44.75 ; 231.331,36.692 231.331,37.828 ; C147_A2.1@232.316,36.559 230.32,36.559 R212_A2.2@230.226,36.654 230.264,36.692 231.227,36.692 231.331,36.796 231.331,37.828 ; 231.331,37.828 230.131,39.028 231.331,37.828
COMML_A1_N: D5_A1.2 J10_A1.2 R225_A1.2 R226_A1.1 | length 9.8
  Top Layer w0.178: R225_A1.2@5.828,34.383 8.05,34.383 8.366,34.7 8.883,34.7 9.094,34.911 D5_A1.2@9.094,34.967 9.126,34.935 9.126,30.804 J10_A1.2@9.287,30.642
  Bottom Layer w0.178: J10_A1.2@9.287,30.642 9.287,29.064 R226_A1.1@9.494,28.858
COMML_A1_P: D5_A1.1 J10_A1.3 R209_A1.1 R210_A1.2 | length 9.8
  Top Layer w0.254: D5_A1.1@10.994,34.967 D5_A1.1@10.994,34.668 ; J10_A1.3@11.827,30.642 10.994,31.475 D5_A1.1@10.994,34.668 ; R210_A1.2@13.923,34.383 13.892,34.415 11.802,34.415 11.722,34.495 11.167,34.495 D5_A1.1@10.994,34.668
  Bottom Layer w0.254: R209_A1.1@11.056,28.859 11.056,28.959 11.608,29.511 11.608,30.423 J10_A1.3@11.827,30.642
COMML_A2_N: D5_A2.2 J10_A2.2 R225_A2.2 R226_A2.1 | length 9.7
  Top Layer w0.178: D5_A2.2@124.117,8.732 124.669,8.732 R225_A2.2@124.669,5.249 ; D5_A2.2@124.669,8.764 128.281,8.764 J10_A2.2@128.442,8.926
  Bottom Layer w0.178: J10_A2.2@128.442,8.926 130.02,8.926 R226_A2.1@130.226,9.132
COMML_A2_P: D5_A2.1 J10_A2.3 R209_A2.1 R210_A2.2 | length 9.7
  Top Layer w0.254: D5_A2.1@124.117,10.632 D5_A2.1@124.416,10.632 ; R210_A2.2@124.669,13.414 124.669,11.44 124.589,11.361 124.589,10.805 D5_A2.1@124.416,10.632 ; J10_A2.3@128.442,11.466 128.312,11.336 125.722,11.336 125.019,10.632 D5_A2.1@124.416,10.632
  Bottom Layer w0.254: J10_A2.3@128.442,11.466 128.661,11.247 129.573,11.247 130.125,10.694 R209_A2.1@130.225,10.694
COMML_N_OPT_A1: C149_A1.2 R221_A1.1 R225_A1.1 T1.4 | length 10.7
  Top Layer w0.178: R225_A1.1@5.828,36.415 R225_A1.1@6.128,36.716 ; T1.4@6.96,44.75 6.96,43.985 6.02,43.045 6.02,39.1 R221_A1.1@5.828,38.907 5.828,37.324 5.938,37.213 5.938,36.905 R225_A1.1@6.128,36.716 ; C149_A1.2@7.717,36.916 6.328,36.916 R225_A1.1@6.128,36.716
COMML_N_OPT_A2: C7.2 C149_A2.2 R221_A2.1 R225_A2.1 T2.4 | length 10.9
  Top Layer w0.254: v2(116.581,7.725) 116.584,7.722 116.584,6.955 116.837,6.702 T2.4@117.737,6.702 118.911,6.702 119.379,6.234 119.379,5.989 119.902,5.466 R221_A2.1@120.177,5.466 R225_A2.1@122.669,5.466 122.669,6.855 C149_A2.2@122.169,7.355
  Bottom Layer w0.254: C7.2@115.466,7.915 115.656,7.725 v2(116.581,7.725)
COMML_P_OPT_A1: C148_A1.1 R210_A1.1 R215_A1.2 T1.6 | length 12.3
  Top Layer w0.254: T1.6@12.04,44.75 12.04,40.12 12.765,39.395 13.436,39.395 R215_A1.2@13.923,38.907 13.923,38.632 13.133,37.842 13.133,37.041 13.758,36.415 R210_A1.1@13.923,36.415 13.507,36 C148_A1.1@12.096,36
COMML_P_OPT_A2: C2.2 C148_A2.1 R210_A2.1 R215_A2.2 T2.6 | length 11.7
  Top Layer w0.254: v2(116.656,10.5) 116.7,10.5 117.204,11.004 117.204,11.529 117.457,11.782 T2.6@117.737,11.782 118.15,11.782 118.882,12.514 118.882,13.175 119.269,13.562 119.902,13.562 120.04,13.562 R215_A2.2@120.177,13.562 120.452,13.562 121.243,12.771 121.953,12.771 122.673,13.491 123.085,13.079 C148_A2.1@123.085,11.735
  Bottom Layer w0.254: C2.2@115.466,10.497 115.47,10.5 v2(116.656,10.5)
CRYSTAL_1.5V_A1: C159_A1.1 C161_A1.2 R56_A1.2 U4_A1.5 U5_A1.5 | length 9
  Top Layer w0.305: C161_A1.2@60.428,15.757 60.561,15.889 61.436,15.889 v2(61.467,15.921) 61.467,15.876 61.637,15.707 U5_A1.5@61.637,14.357
  Bottom Layer w0.305: U4_A1.5@58.35,19.967 58.35,18.746 58.107,18.504 C159_A1.1@58.107,18.454 58.06,18.406 58.06,18.396 58.303,18.153 58.303,18.084 58.603,17.784 59.182,17.784 59.625,17.341 60.267,17.341 60.615,16.993 60.615,16.773 v2(61.467,15.921)
CRYSTAL_1.5V_A2: C159_A2.1 C161_A2.2 R56_A2.2 U4_A2.5 U5_A2.5 | length 9.1
  Top Layer w0.305: C161_A2.2@165.428,15.807 165.428,15.907 165.741,16.219 166.306,16.219 v2(166.338,16.251) 166.338,16.206 166.637,15.907 U5_A2.5@166.637,14.407
  Bottom Layer w0.305: C159_A2.1@163.055,18.501 163.055,18.551 163.103,18.599 163.124,18.599 163.303,18.777 163.303,18.868 163.312,18.877 163.312,19.979 U4_A2.5@163.35,20.017 ; C159_A2.1@163.103,18.403 163.303,18.203 163.303,18.134 163.603,17.834 164.791,17.834 164.97,17.656 164.97,17.539 165.047,17.462 165.247,17.462 165.665,17.043 165.665,16.924 v2(166.338,16.251)
DVDD_A1: C22_A1.2 Q1_A1.2 U1_A1.90 | length 13
  Top Layer w0.178: Q1_A1.2@75.587,6.465 75.526,6.526 75.272,6.526 74.95,6.847 74.95,11.258 74.213,11.995 74.213,13.518 74.284,13.589 74.284,13.797 C22_A1.2@75.044,14.557 75.303,14.816 75.303,15.272 76.446,16.416 76.446,17.762 U1_A1.90@76.457,17.774
DVDD_A2: C22_A2.2 Q1_A2.2 U1_A2.90 | length 13
  Top Layer w0.178: Q1_A2.2@180.587,6.515 180.526,6.576 180.272,6.576 179.95,6.897 179.95,11.308 179.213,12.045 179.213,13.568 179.284,13.639 179.284,13.847 C22_A2.2@180.044,14.607 180.303,14.866 180.303,15.322 181.446,16.466 181.446,17.812 U1_A2.90@181.457,17.824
